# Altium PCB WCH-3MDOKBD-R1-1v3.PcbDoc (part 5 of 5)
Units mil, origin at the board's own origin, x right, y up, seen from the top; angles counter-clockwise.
Board outline 11710.74 x 4477.49 mil, 2 copper layers (Top Layer, Bottom Layer); 422 components, 246 nets, 927 pads, 1295 vias.
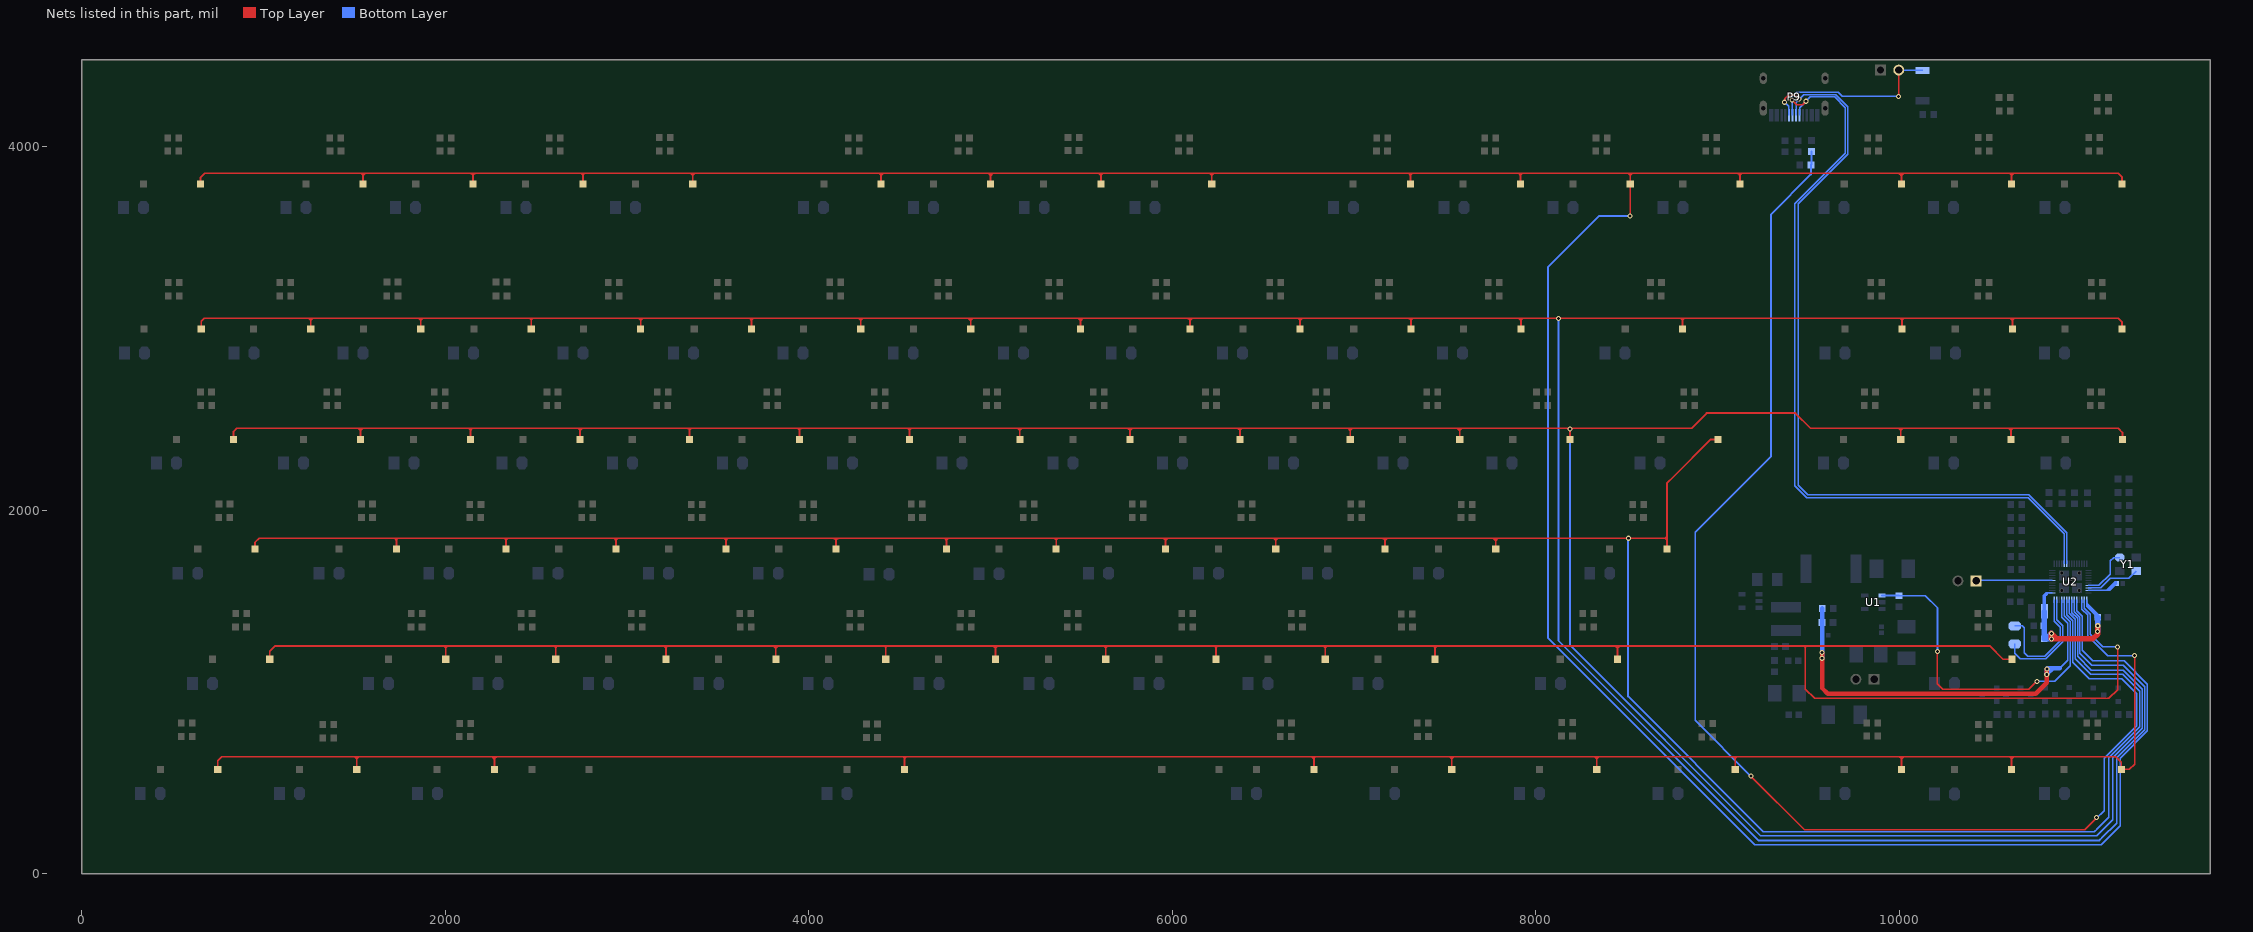
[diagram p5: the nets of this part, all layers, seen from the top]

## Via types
v1: diameter 28, hole 16, Top Layer to Bottom Layer, tented both sides, 1167 vias
v2: diameter 24, hole 12, Top Layer to Bottom Layer, tented both sides, 128 vias

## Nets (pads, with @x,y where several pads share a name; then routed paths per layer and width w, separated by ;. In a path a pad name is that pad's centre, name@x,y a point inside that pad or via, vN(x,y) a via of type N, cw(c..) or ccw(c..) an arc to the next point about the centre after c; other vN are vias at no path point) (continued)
PA0: S1.1 S2.1 S3.1 S4.1 S5.1 S6.1 S36.1 S37.1 S38.1 S39.1 S40.1 S41.1 S42.1 S73.1 S74.1 S75.1 U2.39 | length 19940.3
  Top Layer w10: S1.1@654.86,3793.8 654.86,3829.59 677.54,3852.28 1539.27,3852.28 ; S2.1@1548.73,3793.8 1548.73,3841.66 ; S3.1@2153.27,3793.8 2153.27,3841.02 ; S4.1@2757.8,3793.8 2757.8,3843.06 ; S5.1@3362.34,3793.8 3362.34,3840.86 ; S6.1@4398.26,3793.97 4398.26,3841.44 ; S36.1@5000.82,3793.97 5000.82,3839.61 ; S37.1@5607.27,3794.25 5607.27,3840.64 ; S38.1@6216.74,3794.24 6216.74,3841.77 ; S39.1@7309.83,3793.8 7309.83,3841.63 ; S40.1@7914.98,3793.8 7914.98,3841.77 ; v1@8519.58,3613.77 S41.1@8519.58,3793.88 8519.58,3841.76 ; S42.1@9122.54,3793.8 9122.54,3841.12 ; S73.1@10011.03,3793.8 10011.03,3839.1 ; S74.1@10617.3,3793.8 10617.3,3841.41 ; S75.1@11223.57,3793.8 11223.57,3832.75 11204.04,3852.28 10628.16,3852.28 ; 1539.27,3852.28 1550.27,3852.28 ; 1539.27,3852.28 1539.27,3851.12 1548.73,3841.66 ; 1548.73,3841.66 1559.35,3852.28 ; 1548.73,3841.66 1548.73,3850.74 1550.27,3852.28 ; 1550.27,3852.28 1559.35,3852.28 ; 1559.35,3852.28 2142.01,3852.28 ; 2142.01,3852.28 2154.24,3852.28 ; 2142.01,3852.28 2153.27,3841.02 ; 2153.27,3841.02 2164.52,3852.28 ; 2153.27,3841.02 2153.27,3851.31 2154.24,3852.28 ; 2154.24,3852.28 2164.52,3852.28 ; 2164.52,3852.28 2748.58,3852.28 ; 2748.58,3852.28 2758.87,3852.28 ; 2748.58,3852.28 2757.8,3843.06 ; 2757.8,3843.06 2767.02,3852.28 ; 2757.8,3843.06 2757.8,3851.21 2758.87,3852.28 ; 2758.87,3852.28 2767.02,3852.28 ; 2767.02,3852.28 3351.11,3852.28 ; 3351.11,3852.28 3360.58,3852.28 ; 3351.11,3852.28 3351.11,3852.08 3362.34,3840.86 ; 3360.58,3852.28 3373.76,3852.28 ; 3360.58,3852.28 3362.34,3850.52 3362.34,3840.86 ; 3362.34,3840.86 3373.76,3852.28 ; 3373.76,3852.28 4387.42,3852.28 ; 4387.42,3852.28 4397.66,3852.28 ; 4387.42,3852.28 4398.26,3841.44 ; 4397.66,3852.28 4409.1,3852.28 ; 4397.66,3852.28 4398.26,3851.67 4398.26,3841.44 ; 4398.26,3841.44 4409.1,3852.28 ; 4409.1,3852.28 4989.28,3852.28 ; 4989.28,3852.28 5003.72,3852.28 ; 4989.28,3852.28 4989.28,3851.15 5000.82,3839.61 ; 5000.82,3839.61 5013.48,3852.28 ; 5000.82,3839.61 5000.82,3849.37 5003.72,3852.28 ; 5003.72,3852.28 5013.48,3852.28 ; 5013.48,3852.28 5595.63,3852.28 ; 5595.63,3852.28 5605.54,3852.28 ; 5595.63,3852.28 5607.27,3840.64 ; 5605.54,3852.28 5617.82,3852.28 ; 5605.54,3852.28 5607.27,3850.55 5607.27,3841.72 ; 5607.27,3840.64 5607.27,3841.72 ; 5607.27,3841.72 5617.82,3852.28 ; 5617.82,3852.28 6206.23,3852.28 ; 6206.23,3852.28 6219.21,3852.28 ; 6206.23,3852.28 6216.74,3841.77 ; 6216.74,3841.77 6227.25,3852.28 ; 6216.74,3841.77 6216.74,3849.81 6219.21,3852.28 ; 6219.21,3852.28 6227.25,3852.28 ; 6227.25,3852.28 7299.19,3852.28 ; 7299.19,3852.28 7308.57,3852.28 ; 7299.19,3852.28 7309.83,3841.63 ; 7308.57,3852.28 7320.48,3852.28 ; 7308.57,3852.28 7309.83,3851.02 7309.83,3841.63 ; 7309.83,3841.63 7320.48,3852.28 ; 7320.48,3852.28 7904.48,3852.28 ; 7904.48,3852.28 7914.06,3852.28 ; 7904.48,3852.28 7914.98,3841.77 ; 7914.06,3852.28 7925.48,3852.28 ; 7914.06,3852.28 7914.98,3851.36 7914.98,3841.77 ; 7914.98,3841.77 7925.48,3852.28 ; 7925.48,3852.28 8509.06,3852.28 ; 8509.06,3852.28 8521.05,3852.28 ; 8509.06,3852.28 8519.58,3841.76 ; 8519.58,3841.76 8530.09,3852.28 ; 8519.58,3841.76 8519.58,3850.8 8521.05,3852.28 ; 8521.05,3852.28 8530.09,3852.28 ; 8530.09,3852.28 9112.41,3852.28 ; 9112.41,3852.28 9123.14,3852.28 ; 9112.41,3852.28 9112.41,3851.25 9122.54,3841.12 ; 9122.54,3841.12 9133.7,3852.28 ; 9122.54,3841.12 9122.54,3851.68 9123.14,3852.28 ; 9123.14,3852.28 9133.7,3852.28 ; 9133.7,3852.28 10000.77,3852.28 ; 10000.77,3852.28 10012.2,3852.28 ; 10000.77,3852.28 10000.77,3849.35 10011.03,3839.1 ; 10011.03,3839.1 10011.03,3839.54 ; 10011.03,3839.54 10011.03,3851.11 10012.2,3852.28 ; 10011.03,3839.54 10023.77,3852.28 ; 10012.2,3852.28 10023.77,3852.28 ; 10023.77,3852.28 10606.44,3852.28 ; 10606.44,3852.28 10615.06,3852.28 ; 10606.44,3852.28 10617.3,3841.41 ; 10615.06,3852.28 10628.16,3852.28 ; 10615.06,3852.28 10617.3,3850.04 10617.3,3841.41 ; 10617.3,3841.41 10628.16,3852.28
  Bottom Layer w7: U2.39@10975.43,1506.72 10975.43,1445.44 11005.99,1414.88 11005.99,1229.29 11064.51,1170.76 11235.42,1170.76 11364.29,1041.89 11364.29,784.76 11214.42,634.9 11214.42,262.63 11128.84,177.06
  Bottom Layer w10: v1@8519.58,3617.03 8345.84,3617.03 8067.2,3338.38 8067.2,1989.66 8067.2,1295.05 9203.8,158.45 11110.23,158.45 11128.84,177.06
  other v1: 8518.83,3618.04
PA1: S7.1 S8.1 S9.1 S10.1 S11.1 S12.1 S43.1 S44.1 S45.1 S46.1 S47.1 S48.1 S49.1 S76.1 S77.1 S78.1 S79.1 U2.40 | length 18931
  Top Layer w10: S7.1@658.49,2994.96 658.49,3037.98 675.4,3054.89 1248.97,3054.89 ; S8.1@1260.41,2994.96 1260.41,3043.45 ; S9.1@1866.19,2994.96 1866.19,3044.35 ; S10.1@2473.99,2994.96 2473.99,3045.8 ; S11.1@3075.53,2994.96 3075.53,3043.76 ; S12.1@3685.01,2994.96 3685.01,3044.18 ; S43.1@4286.55,2994.96 4286.55,3044.31 ; S44.1@4890.96,2994.96 4890.96,3041.8 ; S45.1@5495.41,2994.96 5495.41,3042.24 ; S46.1@6097.77,2994.96 6097.77,3043.29 ; S47.1@6703.15,2994.96 6703.15,3043.66 ; S48.1@7312.97,2994.96 7312.97,3043.68 ; S49.1@7917.42,2994.96 7917.42,3044.05 ; S76.1@8806.65,2994.96 8806.65,3043.76 ; S77.1@10014.84,2994.96 10014.84,3043.77 ; S78.1@10621.68,2994.96 10621.68,3043.67 ; S79.1@11224.93,2994.96 11224.93,3033.21 11203.25,3054.89 10632.9,3054.89 ; 1248.97,3054.89 1261.07,3054.89 ; 1248.97,3054.89 1260.41,3043.45 ; 1260.41,3043.45 1271.86,3054.89 ; 1260.41,3043.45 1260.41,3054.23 1261.07,3054.89 ; 1261.07,3054.89 1271.86,3054.89 ; 1271.86,3054.89 1855.65,3054.89 ; 1855.65,3054.89 1866.09,3054.89 ; 1855.65,3054.89 1866.19,3044.35 ; 1866.09,3054.89 1876.74,3054.89 ; 1866.09,3054.89 1866.19,3054.79 1866.19,3044.35 ; 1866.19,3044.35 1876.74,3054.89 ; 1876.74,3054.89 2464.89,3054.89 ; 2464.89,3054.89 2472.86,3054.89 ; 2464.89,3054.89 2473.99,3045.8 ; 2472.86,3054.89 2483.08,3054.89 ; 2472.86,3054.89 2473.99,3053.77 2473.99,3045.8 ; 2473.99,3045.8 2483.08,3054.89 ; 2483.08,3054.89 3064.4,3054.89 ; 3064.4,3054.89 3074.7,3054.89 ; 3064.4,3054.89 3075.53,3043.76 ; 3074.7,3054.89 3086.66,3054.89 ; 3074.7,3054.89 3075.53,3054.07 3075.53,3043.76 ; 3075.53,3043.76 3086.66,3054.89 ; 3086.66,3054.89 3674.29,3054.89 ; 3674.29,3054.89 3685.13,3054.89 ; 3674.29,3054.89 3685.01,3044.18 ; 3685.01,3044.18 3695.72,3054.89 ; 3685.01,3044.18 3685.01,3054.77 3685.13,3054.89 ; 3685.13,3054.89 3695.72,3054.89 ; 3695.72,3054.89 4275.97,3054.89 ; 4275.97,3054.89 4287.94,3054.89 ; 4275.97,3054.89 4286.55,3044.31 ; 4286.55,3044.31 4297.14,3054.89 ; 4286.55,3044.31 4286.55,3053.51 4287.94,3054.89 ; 4287.94,3054.89 4297.14,3054.89 ; 4297.14,3054.89 4877.87,3054.89 ; 4877.87,3054.89 4888.77,3054.89 ; 4877.87,3054.89 4890.96,3041.8 ; 4888.77,3054.89 4902.18,3054.89 ; 4888.77,3054.89 4890.96,3052.7 4890.96,3043.68 ; 4890.96,3041.8 4890.96,3043.68 ; 4890.96,3043.68 4902.18,3054.89 ; 4902.18,3054.89 5482.76,3054.89 ; 5482.76,3054.89 5493.4,3054.89 ; 5482.76,3054.89 5495.41,3042.24 ; 5493.4,3054.89 5508.06,3054.89 ; 5493.4,3054.89 5495.41,3052.88 5495.41,3042.24 ; 5495.41,3042.24 5508.06,3054.89 ; 5508.06,3054.89 6086.17,3054.89 ; 6086.17,3054.89 6098.42,3054.89 ; 6086.17,3054.89 6097.77,3043.29 ; 6097.77,3043.29 6109.38,3054.89 ; 6097.77,3043.29 6097.77,3054.24 6098.42,3054.89 ; 6098.42,3054.89 6109.38,3054.89 ; 6109.38,3054.89 6691.92,3054.89 ; 6691.92,3054.89 6702.66,3054.89 ; 6691.92,3054.89 6703.15,3043.66 ; 6702.66,3054.89 6714.38,3054.89 ; 6702.66,3054.89 6703.15,3054.4 6703.15,3043.66 ; 6703.15,3043.66 6714.38,3054.89 ; 6714.38,3054.89 7301.75,3054.89 ; 7301.75,3054.89 7314.46,3054.89 ; 7301.75,3054.89 7312.97,3043.68 ; 7312.97,3043.68 7324.18,3054.89 ; 7312.97,3043.68 7312.97,3053.4 7314.46,3054.89 ; 7314.46,3054.89 7324.18,3054.89 ; 7324.18,3054.89 7906.57,3054.89 ; 7906.57,3054.89 7915.55,3054.89 ; 7906.57,3054.89 7917.42,3044.05 ; 7915.55,3054.89 7928.27,3054.89 ; 7915.55,3054.89 7917.42,3053.02 7917.42,3044.05 ; 7917.42,3044.05 7928.27,3054.89 ; 7928.27,3054.89 8795.51,3054.89 ; 8795.51,3054.89 8808.68,3054.89 ; 8795.51,3054.89 8806.65,3043.76 ; 8806.65,3043.76 8806.65,3044.01 ; 8806.65,3044.01 8806.65,3052.86 8808.68,3054.89 ; 8806.65,3044.01 8817.53,3054.89 ; 8808.68,3054.89 8817.53,3054.89 ; 8817.53,3054.89 10004.66,3054.89 ; 10004.66,3054.89 10013.43,3054.89 ; 10004.66,3054.89 10004.66,3053.94 10014.84,3043.77 ; 10013.43,3054.89 10023.83,3054.89 ; 10013.43,3054.89 10014.84,3053.49 10014.84,3045.9 ; 10014.84,3043.77 10014.84,3045.9 ; 10014.84,3045.9 10023.83,3054.89 ; 10023.83,3054.89 10610.45,3054.89 ; 10610.45,3054.89 10619.31,3054.89 ; 10610.45,3054.89 10621.68,3043.67 ; 10619.31,3054.89 10632.9,3054.89 ; 10619.31,3054.89 10621.68,3052.52 10621.68,3043.67 ; 10621.68,3043.67 10632.9,3054.89
  Bottom Layer w7: U2.40@10961.65,1506.72 10961.65,1440.84 10992.99,1409.5 10992.99,1211.09 11058.14,1145.94 11231.37,1145.94 11349.33,1027.99 11349.33,791.31 11194.81,636.79 11194.81,277.8 11114.08,197.08
  Bottom Layer w10: v1@8124.41,3054.78 8124.41,1281.87 9223.39,182.89 11099.89,182.89 11114.08,197.08
  other v1: 8123.81,3054.38
PA2: S13.1 S14.1 S15.1 S16.1 S17.1 S18.1 S50.1 S51.1 S52.1 S53.1 S54.1 S55.1 S56.1 S80.1 S81.1 S82.1 U2.41 | length 18038
  Top Layer w10: S13.1@836.42,2388.74 836.42,2432.02 854.25,2449.86 1522.14,2449.86 ; S14.1@1535.07,2388.74 1535.07,2436.93 ; S15.1@2140.31,2388.74 2140.31,2439.5 ; S16.1@2742.63,2388.74 2742.63,2438.94 ; S17.1@3344.57,2388.74 3344.57,2440.48 ; S18.1@3948.78,2388.74 3948.78,2440.32 ; S50.1@4554.49,2388.74 4554.49,2439.79 ; S51.1@5161.33,2388.74 5161.33,2439.86 ; S52.1@5768.19,2388.74 5768.19,2437.6 ; S53.1@6372.38,2388.74 6372.38,2437.85 ; S54.1@6979.24,2388.74 6979.24,2437 ; S55.1@7581.17,2388.74 7581.17,2435.57 ; S56.1@8188.01,2388.74 v1@8188.01,2438.48 ; S80.1@10007.05,2388.74 10007.05,2439.12 ; S81.1@10612.8,2388.74 10612.8,2438.7 ; S82.1@11226.87,2388.74 11226.87,2425.91 11202.93,2449.86 10622.92,2449.86 ; 1522.14,2449.86 1534.65,2449.86 ; 1522.14,2449.86 1535.07,2436.93 ; 1534.65,2449.86 1545.84,2449.86 ; 1534.65,2449.86 1535.07,2449.44 1535.07,2439.08 ; 1535.07,2436.93 1535.07,2439.08 ; 1535.07,2439.08 1545.84,2449.86 ; 1545.84,2449.86 2129.95,2449.86 ; 2129.95,2449.86 2142.83,2449.86 ; 2129.95,2449.86 2140.31,2439.5 ; 2140.31,2439.5 2150.67,2449.86 ; 2140.31,2439.5 2140.31,2447.34 2142.83,2449.86 ; 2142.83,2449.86 2150.67,2449.86 ; 2150.67,2449.86 2731.72,2449.86 ; 2731.72,2449.86 2742.08,2449.86 ; 2731.72,2449.86 2742.63,2438.94 ; 2742.08,2449.86 2753.55,2449.86 ; 2742.08,2449.86 2742.63,2449.31 2742.63,2438.94 ; 2742.63,2438.94 2753.55,2449.86 ; 2753.55,2449.86 3335.2,2449.86 ; 3335.2,2449.86 3343.93,2449.86 ; 3335.2,2449.86 3344.57,2440.48 ; 3343.93,2449.86 3353.95,2449.86 ; 3343.93,2449.86 3344.57,2449.21 3344.57,2440.48 ; 3344.57,2440.48 3353.95,2449.86 ; 3353.95,2449.86 3939.23,2449.86 ; 3939.23,2449.86 3949.8,2449.86 ; 3939.23,2449.86 3948.78,2440.32 ; 3948.78,2440.32 3958.32,2449.86 ; 3948.78,2440.32 3948.78,2448.84 3949.8,2449.86 ; 3949.8,2449.86 3958.32,2449.86 ; 3958.32,2449.86 4544.42,2449.86 ; 4544.42,2449.86 4553.04,2449.86 ; 4544.42,2449.86 4554.49,2439.79 ; 4553.04,2449.86 4564.55,2449.86 ; 4553.04,2449.86 4554.49,2448.41 4554.49,2439.79 ; 4554.49,2439.79 4564.55,2449.86 ; 4564.55,2449.86 5153.23,2449.86 ; 5153.23,2449.86 5161.25,2449.86 ; 5153.23,2449.86 5153.23,2447.95 5161.33,2439.86 ; 5161.25,2449.86 5171.33,2449.86 ; 5161.25,2449.86 5161.33,2449.77 5161.33,2439.86 ; 5161.33,2439.86 5171.33,2449.86 ; 5171.33,2449.86 5757.53,2449.86 ; 5757.53,2449.86 5766.98,2449.86 ; 5757.53,2449.86 5757.53,2448.26 5768.19,2437.6 ; 5766.98,2449.86 5780.45,2449.86 ; 5766.98,2449.86 5768.19,2448.65 5768.19,2437.6 ; 5768.19,2437.6 5780.45,2449.86 ; 5780.45,2449.86 6362.33,2449.86 ; 6362.33,2449.86 6371.49,2449.86 ; 6362.33,2449.86 6362.33,2447.91 6372.38,2437.85 ; 6371.49,2449.86 6383.17,2449.86 ; 6371.49,2449.86 6372.38,2448.96 6372.38,2439.07 ; 6372.38,2437.85 6372.38,2439.07 ; 6372.38,2439.07 6383.17,2449.86 ; 6383.17,2449.86 6966.38,2449.86 ; 6966.38,2449.86 6978.89,2449.86 ; 6966.38,2449.86 6979.24,2437 ; 6978.89,2449.86 6990.3,2449.86 ; 6978.89,2449.86 6979.24,2449.51 6979.24,2438.79 ; 6979.24,2437 6979.24,2438.79 ; 6979.24,2438.79 6990.3,2449.86 ; 6990.3,2449.86 7566.89,2449.86 ; 7566.89,2449.86 7580.39,2449.86 ; 7566.89,2449.86 7581.17,2435.57 ; 7580.39,2449.86 7593.25,2449.86 ; 7580.39,2449.86 7581.17,2449.08 7581.17,2437.77 ; 7581.17,2435.57 7581.17,2437.77 ; 7581.17,2437.77 7593.25,2449.86 ; 7593.25,2449.86 v1@8178.82,2449.86 ; v1@8178.82,2449.86 v1@8189.25,2449.86 ; v1@8178.82,2449.86 8178.82,2447.67 v1@8188.01,2438.48 ; v1@8188.01,2438.48 8188.01,2448.62 v1@8189.25,2449.86 ; v1@8188.01,2438.48 8189.47,2438.48 v1@8200.85,2449.86 ; v1@8189.25,2449.86 v1@8200.85,2449.86 ; v1@8200.85,2449.86 8856.45,2449.86 8939.49,2532.89 9427.71,2532.89 9510.75,2449.86 9996.32,2449.86 ; 9996.32,2449.86 10006.93,2449.86 ; 9996.32,2449.86 10007.05,2439.12 ; 10006.93,2449.86 10017.78,2449.86 ; 10006.93,2449.86 10007.05,2449.74 10007.05,2439.12 ; 10007.05,2439.12 10017.78,2449.86 ; 10017.78,2449.86 10601.64,2449.86 ; 10601.64,2449.86 10612.82,2449.86 ; 10601.64,2449.86 10612.8,2438.7 ; 10612.8,2438.7 10622.92,2448.81 10622.92,2449.86 ; 10612.8,2438.7 10612.8,2449.84 ; 10612.82,2449.86 10622.92,2449.86
  Bottom Layer w7: U2.41@10947.87,1506.72 10947.87,1436.23 10979.52,1404.58 10979.52,1195.96 11055.79,1119.69 11230.23,1119.69 11335.67,1014.24 11335.67,798.8 11174.17,637.3 11174.17,297.35 11096.57,219.75
  Bottom Layer w10: v1(8188.2,2446.56) 8188.2,1255.65 9235.61,208.24 11085.05,208.24 11096.57,219.75
PA3: S19.1 S20.1 S21.1 S22.1 S23.1 S24.1 S57.1 S58.1 S59.1 S60.1 S61.1 S62.1 S63.1 S83.1 U2.42 | length 14956.7
  Top Layer w10: S19.1@953.93,1785.35 953.93,1821.64 976.86,1844.56 1721.65,1844.56 ; S20.1@1731.56,1785.35 1731.56,1834.65 ; S21.1@2335.05,1785.35 2335.05,1835.06 ; S22.1@2939.64,1785.35 2939.64,1833.7 ; S23.1@3545.39,1785.35 3545.39,1834.65 ; S24.1@4150.01,1785.35 4150.01,1833.19 ; S57.1@4757.72,1785.35 4757.72,1834.15 ; S58.1@5361.23,1785.35 5361.23,1834.99 ; S59.1@5963.21,1785.35 5963.21,1832.28 ; S60.1@6568.85,1785.35 6568.85,1834.11 ; S61.1@7170.54,1785.35 7170.54,1832.68 ; S62.1@7778.96,1785.35 7778.96,1831.94 ; S83.1@8720.81,1785.35 8720.81,1835.31 ; S63.1@9001.52,2388.74 8962.94,2388.74 8757.08,2182.88 8720.81,2146.62 8720.81,1864.44 8720.81,1854.14 ; 1721.65,1844.56 1730.74,1844.56 ; 1721.65,1844.56 1731.56,1834.65 ; 1730.74,1844.56 1740.55,1844.56 ; 1730.74,1844.56 1731.56,1843.75 1731.56,1835.56 ; 1731.56,1834.65 1731.56,1835.56 ; 1731.56,1835.56 1740.55,1844.56 ; 1740.55,1844.56 2325.55,1844.56 ; 2325.55,1844.56 2335.45,1844.56 ; 2325.55,1844.56 2335.05,1835.06 ; 2335.05,1835.06 2344.55,1844.56 ; 2335.05,1835.06 2335.05,1844.16 2335.45,1844.56 ; 2335.45,1844.56 2344.55,1844.56 ; 2344.55,1844.56 2928.78,1844.56 ; 2928.78,1844.56 2941.17,1844.56 ; 2928.78,1844.56 2939.64,1833.7 ; 2939.64,1833.7 2950.5,1844.56 ; 2939.64,1833.7 2939.64,1843.03 2941.17,1844.56 ; 2941.17,1844.56 2950.5,1844.56 ; 2950.5,1844.56 3535.49,1844.56 ; 3535.49,1844.56 3544.21,1844.56 ; 3535.49,1844.56 3545.39,1834.65 ; 3544.21,1844.56 3555.3,1844.56 ; 3544.21,1844.56 3545.39,1843.38 3545.39,1834.65 ; 3545.39,1834.65 3555.3,1844.56 ; 3555.3,1844.56 4138.64,1844.56 ; 4138.64,1844.56 4150.93,1844.56 ; 4138.64,1844.56 4150.01,1833.19 ; 4150.01,1833.19 4161.38,1844.56 ; 4150.01,1833.19 4150.01,1843.63 4150.93,1844.56 ; 4150.93,1844.56 4161.38,1844.56 ; 4161.38,1844.56 4747.3,1844.56 ; 4747.3,1844.56 4757.12,1844.56 ; 4747.3,1844.56 4757.72,1834.15 ; 4757.12,1844.56 4768.13,1844.56 ; 4757.12,1844.56 4757.72,1843.97 4757.72,1834.15 ; 4757.72,1834.15 4768.13,1844.56 ; 4768.13,1844.56 5351.66,1844.56 ; 5351.66,1844.56 5361.7,1844.56 ; 5351.66,1844.56 5361.23,1834.99 ; 5361.23,1834.99 5361.23,1835.43 ; 5361.23,1835.43 5361.23,1844.09 5361.7,1844.56 ; 5361.23,1835.43 5370.35,1844.56 ; 5361.7,1844.56 5370.35,1844.56 ; 5370.35,1844.56 5950.93,1844.56 ; 5950.93,1844.56 5961.4,1844.56 ; 5950.93,1844.56 5963.21,1832.28 ; 5961.4,1844.56 5973.56,1844.56 ; 5961.4,1844.56 5963.21,1842.74 5963.21,1832.28 ; 5963.21,1832.28 5973.56,1842.63 5973.56,1844.56 ; 5973.56,1844.56 6558.41,1844.56 ; 6558.41,1844.56 6571.18,1844.56 ; 6558.41,1844.56 6568.85,1834.11 ; 6568.85,1834.11 6579.3,1844.56 ; 6568.85,1834.11 6568.85,1842.24 6571.18,1844.56 ; 6571.18,1844.56 6579.3,1844.56 ; 6579.3,1844.56 7158.67,1844.56 ; 7158.67,1844.56 7170.96,1844.56 ; 7158.67,1844.56 7170.54,1832.68 ; 7170.54,1832.68 7182.42,1844.56 ; 7170.54,1832.68 7170.54,1844.14 7170.96,1844.56 ; 7170.96,1844.56 7182.42,1844.56 ; 7182.42,1844.56 7766.34,1844.56 ; 7766.34,1844.56 7779.41,1844.56 ; 7766.34,1844.56 7778.96,1831.94 ; 7778.96,1831.94 7791.58,1844.56 ; 7778.96,1831.94 7778.96,1844.1 7779.41,1844.56 ; 7779.41,1844.56 7791.58,1844.56 ; 7791.58,1844.56 8711.24,1844.56 ; 8711.24,1844.56 8720.81,1854.14 ; 8711.24,1844.56 8719.6,1844.56 8720.81,1845.78 ; 8711.24,1844.56 8720.49,1835.31 8720.81,1835.31 ; 8720.81,1835.31 8720.81,1845.78 ; 8720.81,1845.78 8720.81,1854.14
  Bottom Layer w7: U2.42@10934.09,1506.72 10934.09,1431.63 10966.52,1399.2 10966.52,1181.34 11052.04,1095.82 11228.85,1095.82 11321.65,1003.01 11321.65,806.51 11152.74,637.6 11152.74,311.28 11086.6,245.14
  Bottom Layer w10: v1@8506.05,1843.05 8507.18,1841.92 8507.18,974.97 9251.51,230.64 11072.1,230.64 11086.6,245.14
  other v1: 8508.49,1844.88
PA4: S25.1 S26.1 S27.1 S28.1 S29.1 S30.1 S64.1 S65.1 S66.1 S67.1 S68.1 S69.1 S84.1 U2.36 | length 13485.5
  Top Layer w7: 9473.87,1252.82 9482.67,1244.02 ; 9482.67,1252.19 9482.67,1244.02 ; 9492.71,1252.82 9491.47,1252.82 9482.67,1244.02 ; v1(11199.84,1247.03) 11199.84,1012.28 11151.42,963.86 9532.9,963.86 9482.67,1014.08 9482.67,1244.02
  Top Layer w10: S25.1@1035.51,1178.83 1035.51,1223.79 1064.53,1252.82 1992.05,1252.82 ; S26.1@2003.11,1178.83 2003.11,1241.75 ; S27.1@2608.46,1178.83 2608.46,1243.41 ; S28.1@3214.49,1178.83 3214.49,1242.03 ; S29.1@3819.1,1178.83 3819.1,1238.75 ; S30.1@4423.72,1178.83 4423.72,1243.73 ; S64.1@5028.29,1178.83 5028.29,1238.51 ; S65.1@5634.21,1178.83 5634.21,1241.74 ; S66.1@6240.4,1178.83 6240.4,1241.79 ; S67.1@6841.4,1178.83 6841.4,1242.41 ; S68.1@7445.87,1178.83 7445.87,1241.42 ; S69.1@8449.06,1178.83 8449.06,1238.2 ; 9491.47,1252.82 9473.87,1252.82 8463.01,1252.82 ; 9492.71,1252.82 10495.72,1252.82 10569.71,1178.83 S84.1@10620.02,1178.83 ; 1992.05,1252.82 2002.15,1252.82 ; 1992.05,1252.82 2003.11,1241.75 ; 2002.15,1252.82 2014.18,1252.82 ; 2002.15,1252.82 2003.11,1251.85 2003.11,1241.75 ; 2003.11,1241.75 2014.18,1252.82 ; 2014.18,1252.82 2599.05,1252.82 ; 2599.05,1252.82 2607.51,1252.82 ; 2599.05,1252.82 2608.46,1243.41 ; 2607.51,1252.82 2617.86,1252.82 ; 2607.51,1252.82 2608.46,1251.87 2608.46,1243.41 ; 2608.46,1243.41 2617.86,1252.82 ; 2617.86,1252.82 3203.7,1252.82 ; 3203.7,1252.82 3213.64,1252.82 ; 3203.7,1252.82 3214.49,1242.03 ; 3213.64,1252.82 3225.27,1252.82 ; 3213.64,1252.82 3214.49,1251.97 3214.49,1242.03 ; 3214.49,1242.03 3225.27,1252.82 ; 3225.27,1252.82 3805.04,1252.82 ; 3805.04,1252.82 3817.62,1252.82 ; 3805.04,1252.82 3819.1,1238.75 ; 3817.62,1252.82 3833.16,1252.82 ; 3817.62,1252.82 3819.1,1251.34 3819.1,1238.75 ; 3819.1,1238.75 3833.16,1252.82 ; 3833.16,1252.82 4414.63,1252.82 ; 4414.63,1252.82 4427.41,1252.82 ; 4414.63,1252.82 4423.72,1243.73 ; 4423.72,1243.73 4432.81,1252.82 ; 4423.72,1243.73 4423.72,1249.12 4427.41,1252.82 ; 4427.41,1252.82 4432.81,1252.82 ; 4432.81,1252.82 5015.11,1252.82 ; 5015.11,1252.82 5027.37,1252.82 ; 5015.11,1252.82 5015.11,1251.68 5028.29,1238.51 ; 5027.37,1252.82 5039.33,1252.82 ; 5027.37,1252.82 5028.29,1251.9 5028.29,1241.78 ; 5028.29,1238.51 5028.29,1241.78 ; 5028.29,1241.78 5039.33,1252.82 ; 5039.33,1252.82 5623.13,1252.82 ; 5623.13,1252.82 5634.56,1252.82 ; 5623.13,1252.82 5634.21,1241.74 ; 5634.21,1241.74 5645.28,1252.82 ; 5634.21,1241.74 5634.21,1252.46 5634.56,1252.82 ; 5634.56,1252.82 5645.28,1252.82 ; 5645.28,1252.82 6229.37,1252.82 ; 6229.37,1252.82 6239.97,1252.82 ; 6229.37,1252.82 6240.4,1241.79 ; 6239.97,1252.82 6251.44,1252.82 ; 6239.97,1252.82 6240.4,1252.38 6240.4,1241.79 ; 6240.4,1241.79 6251.44,1252.82 ; 6251.44,1252.82 6830.98,1252.82 ; 6830.98,1252.82 6839.39,1252.82 ; 6830.98,1252.82 6841.4,1242.41 ; 6839.39,1252.82 6851.81,1252.82 ; 6839.39,1252.82 6841.4,1250.81 6841.4,1242.41 ; 6841.4,1242.41 6851.81,1252.82 ; 6851.81,1252.82 7434.48,1252.82 ; 7434.48,1252.82 7442.33,1252.82 ; 7434.48,1252.82 7445.87,1241.42 ; 7442.33,1252.82 7456.38,1252.82 ; 7442.33,1252.82 7445.87,1249.27 7445.87,1241.42 ; 7445.87,1241.42 7456.38,1251.93 7456.38,1252.82 ; 7456.38,1252.82 8434.72,1252.82 ; 8434.72,1252.82 8445.47,1252.82 ; 8434.72,1252.82 8434.72,1252.54 8449.06,1238.2 ; 8445.47,1252.82 8463.01,1252.82 ; 8445.47,1252.82 8449.06,1249.23 8449.06,1238.87 ; 8449.06,1238.2 8449.06,1238.87 ; 8449.06,1238.87 8463.01,1252.82
  Bottom Layer w7: U2.36@11016.77,1506.72 11016.77,1459.26 11049.15,1426.88 11049.15,1317.4 11119.52,1247.03 v1(11199.84,1247.03)
PA5: S31.1 S32.1 S33.1 S34.1 S35.1 S71.1 S72.1 S85.1 S86.1 S87.1 S_Fn1.1 U2.37 | length 12690.1
  Top Layer w7: S87.1@11220.65,573.38 11265.28,573.38 11293.58,601.68 v1@11293.58,1198.59
  Top Layer w10: S31.1@748.99,573.38 748.99,620.81 771.12,642.94 1502.84,642.94 ; S32.1@1513.74,573.38 1513.74,631.56 ; S33.1@2271.01,573.38 2271.01,629.75 ; S34.1@4526.93,568.53 4526.93,634.47 ; S35.1@6778.66,573.38 6778.66,631.31 ; S_Fn1.1@7536.95,573.38 7536.95,631.31 ; S71.1@8335.08,573.38 8335.08,630.33 ; S72.1@9096.51,573.38 9096.51,631.6 ; S85.1@10011.76,573.38 10011.76,631.13 ; S86.1@10617.3,573.38 10617.3,632.12 ; S87.1@11220.65,573.38 11220.65,612.79 11190.5,642.94 10628.07,642.94 ; 1502.84,642.94 1515.17,642.94 ; 1502.84,642.94 1502.84,642.46 1513.74,631.56 ; 1513.74,631.56 1525.12,642.94 ; 1513.74,631.56 1513.74,641.51 1515.17,642.94 ; 1515.17,642.94 1525.12,642.94 ; 1525.12,642.94 2257.82,642.94 ; 2257.82,642.94 2271.59,642.94 ; 2257.82,642.94 2271.01,629.75 ; 2271.01,629.75 2271.01,630.9 ; 2271.01,630.9 2271.01,642.36 2271.59,642.94 ; 2271.01,630.9 2283.05,642.94 ; 2271.59,642.94 2283.05,642.94 ; 2283.05,642.94 4518.46,642.94 ; 4518.46,642.94 4526.93,642.94 ; 4518.46,642.94 4526.93,634.47 ; 4526.93,634.47 4527.57,634.47 4536.04,642.94 ; 4526.93,634.47 4526.93,642.94 ; 4526.93,642.94 4536.04,642.94 ; 4536.04,642.94 6769.94,642.94 ; 6769.94,642.94 6780.28,642.94 ; 6769.94,642.94 6769.94,640.03 6778.66,631.31 ; 6778.66,631.31 6778.66,633.92 ; 6778.66,633.92 6778.66,641.32 6780.28,642.94 ; 6778.66,633.92 6787.68,642.94 ; 6780.28,642.94 6787.68,642.94 ; 6787.68,642.94 7525.32,642.94 ; 7525.32,642.94 7536.61,642.94 ; 7525.32,642.94 7536.95,631.31 ; 7536.61,642.94 7548.59,642.94 ; 7536.61,642.94 7536.95,642.59 7536.95,631.31 ; 7536.95,631.31 7548.59,642.94 ; 7548.59,642.94 8322.47,642.94 ; 8322.47,642.94 8333.97,642.94 ; 8322.47,642.94 8335.08,630.33 ; 8333.97,642.94 8345.72,642.94 ; 8333.97,642.94 8335.08,641.84 8335.08,632.29 ; 8335.08,630.33 8335.08,632.29 ; 8335.08,632.29 8345.72,642.94 ; 8345.72,642.94 9085.57,642.94 ; 9085.57,642.94 9096.5,642.94 ; 9085.57,642.94 9085.57,642.54 9096.51,631.6 ; 9096.51,631.6 9096.51,633.28 ; 9096.51,633.28 9096.51,642.93 ; 9096.51,633.28 9106.17,642.94 ; 9096.5,642.94 9106.17,642.94 ; 9106.17,642.94 9999.95,642.94 ; 9999.95,642.94 10009.33,642.94 ; 9999.95,642.94 10011.76,631.13 ; 10009.33,642.94 10021.23,642.94 ; 10009.33,642.94 10011.76,640.51 10011.76,631.13 ; 10011.76,631.13 10021.23,640.6 10021.23,642.94 ; 10021.23,642.94 10606.47,642.94 ; 10606.47,642.94 10616.71,642.94 ; 10606.47,642.94 10617.3,632.12 ; 10616.71,642.94 10628.07,642.94 ; 10616.71,642.94 10617.3,642.36 10617.3,632.17 ; 10617.3,632.12 10617.3,632.17 ; 10617.3,632.17 10628.07,642.94
  Bottom Layer w7: U2.37@11002.99,1506.72 11002.99,1454.65 11034.96,1422.68 11034.96,1308.66 11145.03,1198.59 v1@11293.58,1198.59
  other v1: 11292.18,1198.87
PA9: P7.1 U2.6 | length 420.6
  Bottom Layer w7: P7.1@10421.86,1610.46 10424.01,1612.6 U2.6@10841.57,1612.6
PA10: U2.48 Y2.2 | length 673.5
  Bottom Layer w7: Y2.2@10634.75,1362.41 10676.81,1362.41 10687.13,1352.08 10687.13,1214.74 10705.84,1196.02 10799.73,1196.02 10884.05,1280.34 10884.05,1354.34 10851.41,1386.97 U2.48@10851.41,1506.72
PA11: U2.47 Y2.1 | length 610.9
  Bottom Layer w7: Y2.1@10634.75,1263.98 10634.75,1212.64 10664.36,1183.02 10805.6,1183.02 10899.11,1276.54 10899.11,1362.6 10865.19,1396.52 U2.47@10865.19,1506.72
PA13: C5.2 R121.1 R129.2 U2.45 | length 2378.2
  Top Layer w25: v1(9574.16,1216.63) 9574.16,1020.62 9605.8,988.98 10750.06,988.98 10810.56,1049.48 10810.56,1125.11 v1(10811.41,1125.95)
  Bottom Layer w7: 10881.56,1129.74 10926.2,1174.38 10926.2,1377.22 10892.75,1410.67 U2.45@10892.75,1506.72
  Bottom Layer w25: v1@9574.22,1184.26 C5.2@9574.22,1311.74 R129.2@9574.22,1380.06 9574.22,1457.51 R121.1@9574.94,1458.22 ; v1(10811.41,1125.95) v1@10811.41,1098.63 ; v1@10812.43,1129.74 10842.51,1129.74 ; 10881.56,1129.74 10842.51,1129.74 ; v1@10811.41,1098.63 10842.51,1129.74 ; v1@10811.41,1098.63 10810.53,1097.76 v1(10810.53,1095.6) 10811.41,1096.47 v1@10811.41,1098.63
  other v1: 9573.64,1184.88
PA14: R117.1 U1.1 U2.44 | length 1926.6
  Top Layer w7: v1(10209.21,1221.25) 10209.21,1044.66 10208.59,1044.04 10239.33,1013.29 10711.87,1013.29 v1(10755.97,1057.39)
  Bottom Layer w7: v1(10755.97,1057.39) 10853.74,1057.39 10939.29,1142.94 10939.29,1384.38 10906.53,1417.14 U2.44@10906.53,1506.72
  Bottom Layer w10: U1.1@9904.01,1530.18 9996.38,1530.18 R117.1@9997.61,1528.94 10142.95,1528.94 10209.21,1462.69 v1(10209.21,1221.25)
PA15: R120.1 R128.2 U2.43 | length 7436
  Top Layer w10: v1(9182.95,536.58) 9477.85,241.67 11018.51,241.67 v1(11085.08,308.25)
  Bottom Layer w7: U2.43@10920.31,1506.72 10920.31,1424.55 10953.52,1391.34 10953.52,1162.17 11044.69,1071 11222.83,1071
  Bottom Layer w10: v1(9182.95,536.58) 8877.01,842.51 8877.01,1877.89 9293.79,2294.66 9293.79,3627.12 9513.18,3846.51 R128.2@9513.18,3898.85 9515.84,3901.51 R120.1@9515.84,3972.2 ; v1@11084.03,304.4 11126.3,346.67 11126.3,635.29 11304.55,813.54 11304.55,989.28 11222.83,1071
UD+: P6.2 P9.A6 P9.B6 S70.3 U2.15 | length 5367.2
  Top Layer w7: v1(9409.53,4255.05) 9434.16,4230.42 9467.9,4230.42 v1(9485.92,4248.44) ; v1@9996.11,4275.54 P6.2@9996.11,4420.24
  Bottom Layer w7: P9.A6@9411.38,4172.15 9411.38,4275.03 9434.5,4298.14 9662.75,4298.14 9685.36,4275.54 v1(9995.02,4275.54) ; P9.B6@9450.75,4172.15 9450.75,4213.75 9509.14,4272.14 9644.47,4272.14 9702.7,4213.91 9702.7,3962.68 9424.66,3684.63 9424.66,2133.24 9489.51,2068.39 10708.31,2068.39 10906.92,1869.79 10906.92,1838.5 U2.15@10906.53,1704.68 ; P6.2@9998.33,4418.02 S70.3@10127.09,4418.02
UD-: P9.A7 P9.B7 U2.16 | length 4551.6
  Top Layer w7: v1(9367.93,4243.38) 9367.93,4261.58 9387.23,4280.87 9427.68,4280.87 v1(9447.45,4261.1)
  Bottom Layer w7: v1@9364.82,4246.94 9391.7,4220.06 P9.B7@9391.7,4172.15 ; P9.A7@9431.07,4172.15 9431.07,4243.35 9472.86,4285.14 9649.86,4285.14 9715.7,4219.3 9715.7,3962.16 9715.7,3957.29 9709.15,3950.73 9624.43,3866.02 9443.41,3685 9443.41,2137 9495.48,2084.93 10711.35,2084.93 10920.31,1875.97 U2.16@10920.31,1704.68
VDCIA: C8.2 C9.2 C14.2 L2.2 U2.1 U2.35 | length 1441.8
  Top Layer w30: v1@11091.5,1363.19 11091.5,1319.22 11062.98,1290.7 10866.43,1290.7 ; 10866.43,1290.7 v1(10836.12,1321.01) v1(10836.12,1290.7) 10866.43,1290.7
  Bottom Layer w7: L2.2@10795.4,1441.07 L2.2@10797.66,1443.33 ; U2.1@10841.57,1543.71 10818.58,1543.71 ; U2.35@11030.55,1506.72 11030.55,1486.84 ; C14.2@11087.52,1412.47 11030.55,1469.45 ; C14.2@11091.5,1405.85 11091.5,1408.5 C14.2@11091.5,1417.84 ; C14.2@11092.82,1407.17 11092.82,1416.52 C14.2@11091.5,1417.84 ; L2.2@10797.66,1443.33 10802.62,1448.29 10802.62,1527.74 ; L2.2@10797.66,1443.33 10797.66,1522.78 ; L2.2@10797.66,1443.33 10791.56,1449.42 10791.56,1527.97 10797.66,1534.06 ; 10797.66,1522.78 10802.62,1527.74 ; 10797.66,1522.78 10797.66,1534.06 ; 10797.66,1534.06 10805.66,1534.06 10807.3,1532.42 ; 10797.66,1534.06 10807.3,1543.71 ; 10802.62,1527.74 10807.3,1532.42 ; 10807.3,1532.42 10818.58,1543.71 ; 10807.3,1532.42 10807.3,1543.71 ; 10807.3,1543.71 10818.58,1543.71 ; 11030.55,1469.45 11030.55,1478.79 ; 11030.55,1469.45 11039.89,1469.45 ; 11030.55,1478.79 11030.55,1486.84 ; 11030.55,1478.79 11038.6,1478.79 ; 11030.55,1478.79 11039.89,1469.45 ; 11030.55,1486.84 11038.6,1478.79 ; 11038.6,1478.79 11091.5,1425.89 C14.2@11091.5,1417.84 ; 11039.89,1469.45 C14.2@11091.5,1417.84
  Bottom Layer w30: C8.2@10795.4,1292.32 L2.2@10795.4,1441.07 ; C8.2@10796.11,1292.32 C8.2@10807.43,1292.32 ; C14.2@11087.52,1412.47 11091.5,1408.5 11092.82,1407.17 11091.5,1405.85 v1@11091.5,1332.25 ; C8.2@10807.43,1292.32 v1(10836.12,1321.01) v1(10836.12,1290.7) 10834.51,1292.32 C8.2@10807.43,1292.32
  other v1: 11090.44,1332.25 11090.93,1363.19
VINTA: C7.2 U2.33 | length 315.4
  Bottom Layer w7: U2.33@11039.89,1557.49 11140.02,1557.49 ; C7.2@11194.22,1604.58 11187.11,1604.58 11178.59,1596.06 ; 11140.02,1557.49 11148.24,1557.49 ; 11140.02,1557.49 11178.59,1596.06 ; 11148.24,1557.49 11156.24,1557.49 C7.2@11194.81,1596.06 C7.2@11186.81,1596.06 ; 11148.24,1557.49 C7.2@11186.81,1596.06 ; 11178.59,1596.06 C7.2@11186.81,1596.06
X32MI: U2.32 Y1.3 | length 300.3
  Bottom Layer w7: U2.32@11039.89,1571.27 11107.17,1571.27 11159.99,1624.09 11262.24,1624.09 Y1.3@11301.9,1663.76
X32MO: U2.31 Y1.1 | length 277.6
  Bottom Layer w7: U2.31@11039.89,1585.05 11096.86,1585.05 11158.99,1647.18 11158.99,1719.88 11177.67,1738.56 Y1.1@11211.35,1738.56
pads on no net: P9.A8 P9.B8 S88.1 S88.2 S89.1 S89.2 U1.3

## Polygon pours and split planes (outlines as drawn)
BT- on Bottom Layer "GND" (hatched Horizontal grid 8 track 8, remove dead copper, pour order 1): 11710.74,4477.49 11710.74,0 0,0 0,4477.49
BT- on Bottom Layer "GND1" (hatched Horizontal grid 8 track 8, remove dead copper, pour order 3): 11013.8,1575.74 11013.8,1440.99 11441.92,1440.99 11441.92,1582.06
BT- on Top Layer "GND" (hatched Horizontal grid 8 track 8, remove dead copper, pour order 0): 0,4477.49 0,0 11710.74,0 11710.74,4477.49

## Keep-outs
Keep-Out Layer:
  lines w8: 0,0 11710.66,0 11710.66,4477.97 0,4477.97 0,0

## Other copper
Top Layer:
  rectangle net BT-: 10871.04,1534.94 11010.24,1676.49
Bottom Layer:
  rectangle net BT-: 11373.76,1548.89 11446.6,1584.33
  rectangle net BT-: 11404.52,1529.19 11434.63,1606.16
  region net BT-: 11425.68,1527.03 11425.68,1642.44 11383.11,1642.44 11383.11,1527.03
  pour cut-out: 9453.32,1768.79 9453.32,1582.84 9796.7,1582.84 9796.7,1768.79
  pour cut-out: 9276.36,1499.22 9276.36,1302.37 9473.21,1302.37 9473.21,1499.22
Multi-Layer:
  pour cut-out: 11711.79,4477.49 11430.63,4477.49 11430.63,0 11711.79,0

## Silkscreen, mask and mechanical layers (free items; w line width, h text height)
Top Overlay:
  drawing of 378 lines, arcs and shapes, not listed
  text "键盘指示灯" at 10635.17,4411.87 h60
  text "WCH-3MODEKBD-R1-1v3" at 9286.34,1929.11 h60
Bottom Overlay:
  lines w10: 9391.94,3897.72 9411.03,3916.8 9411.03,3941.59
  text "UD+" at 9977.79,4251.81 h35 r270
  text "+3V3" at 9879.45,4215.79 h35 r270
  text "BT-" at 10298.28,1449.66 h35 r270
  text "TXD1" at 10403.59,1419.76 h35 r270
  text "BT+" at 9781.85,966.88 h35
  text "BT-" at 9905.9,966.89 h35
Mechanical 1:
  the board outline again, w10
